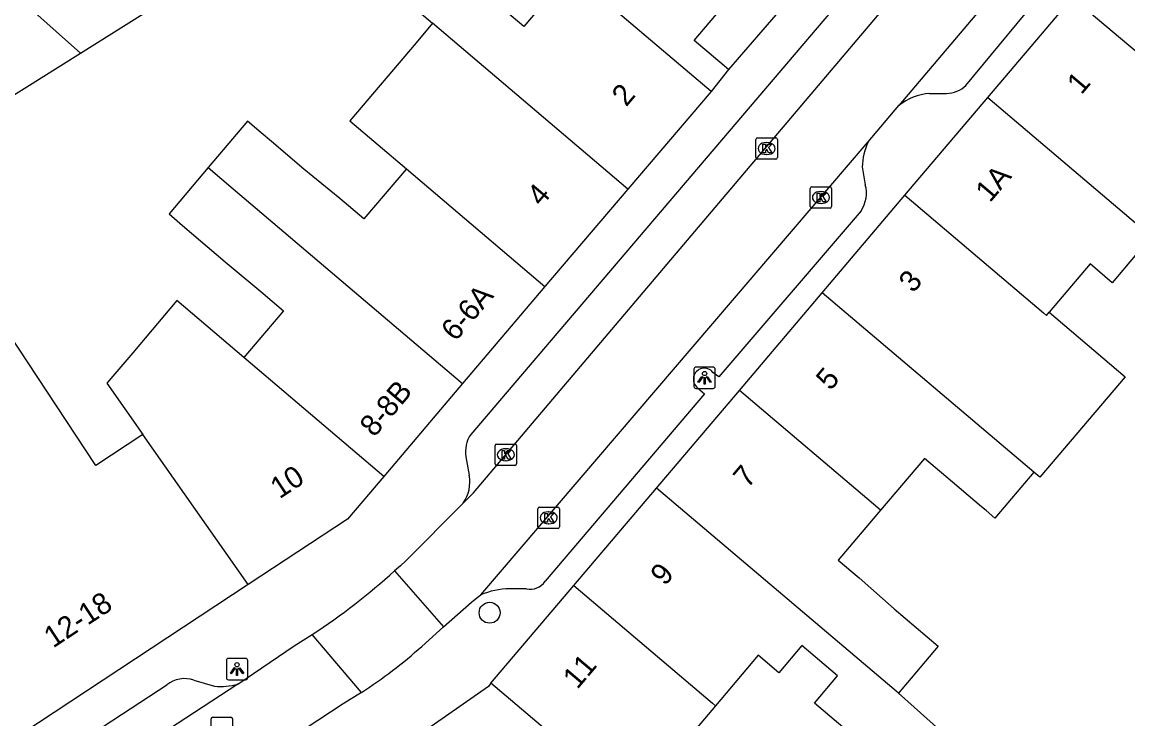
# Model space of a CAD drawing. Extents: x 161801 to 162379, y 382315 to 382832.
# Drawn here: x 162101.6 to 162153.3, y 382604.8 to 382637.3 of the extents above; entities that cross this region are included whole.
import ezdxf

# ---------------------------------------------------------------- set-up
doc = ezdxf.new("R2010")
doc.units = 0
for name, color, linetype in [('IMGEO_Boom', 7, 'Continuous'), ('IMGEO_Kolk', 7, 'Continuous'), ('IMGEO_Lichtpunt', 7, 'Continuous'), ('IMGEO_Pand', 7, 'Continuous'), ('IMGEO_Pand_nummerreeks', 7, 'Continuous'), ('IMGEO_Rijbaan_lokaal_open', 7, 'Continuous'), ('IMGEO_Rioolput', 7, 'Continuous'), ('IMGEO_Voetpad_open', 7, 'Continuous')]:
    doc.layers.add(name, color=color, linetype=linetype)

msp = doc.modelspace()

# ---------------------------------------------------------------- linework, layer by layer
at = {"layer": 'IMGEO_Boom'}
msp.add_circle((162123.501, 382609.719), 0.489, dxfattribs=at)
at = {"layer": 'IMGEO_Kolk'}
for p, q in [((162135.951, 382630.986), (162135.951, 382631.838)), ((162136.026, 382631.912), (162136.878, 382631.912)), ((162136.439, 382631.692), (162136.464, 382631.692)), ((162136.952, 382631.838), (162136.952, 382630.986)), ((162136.462, 382631.132), (162136.437, 382631.132)), ((162136.878, 382630.912), (162136.026, 382630.912)), ((162138.487, 382628.698), (162138.487, 382629.55)), ((162138.562, 382629.624), (162139.414, 382629.624)), ((162138.975, 382629.404), (162139, 382629.404)), ((162139.488, 382629.55), (162139.488, 382628.698)), ((162139.414, 382628.624), (162138.562, 382628.624)), ((162138.998, 382628.844), (162138.973, 382628.844)), ((162123.759, 382616.675), (162123.759, 382617.527)), ((162123.834, 382617.601), (162124.686, 382617.601)), ((162124.76, 382617.527), (162124.76, 382616.675)), ((162124.247, 382617.381), (162124.272, 382617.381)), ((162124.686, 382616.601), (162123.834, 382616.601)), ((162124.27, 382616.821), (162124.245, 382616.821)), ((162125.761, 382613.728), (162125.761, 382614.58)), ((162125.836, 382614.654), (162126.688, 382614.654)), ((162126.249, 382614.434), (162126.274, 382614.434)), ((162126.762, 382614.58), (162126.762, 382613.728)), ((162126.272, 382613.874), (162126.247, 382613.874)), ((162126.688, 382613.654), (162125.836, 382613.654))]:
    msp.add_line(p, q, dxfattribs=at)
for points in [[(162135.951, 382630.986), (162135.951, 382631.838)], [(162136.026, 382631.912), (162136.878, 382631.912)], [(162136.272, 382631.612), (162136.395, 382631.612), (162136.395, 382631.461), (162136.525, 382631.612), (162136.689, 382631.612), (162136.543, 382631.461), (162136.696, 382631.212), (162136.544, 382631.212), (162136.459, 382631.376), (162136.395, 382631.309), (162136.395, 382631.212), (162136.272, 382631.212), (162136.272, 382631.612)], [(162136.952, 382631.838), (162136.952, 382630.986)], [(162136.878, 382630.912), (162136.026, 382630.912)], [(162138.487, 382628.698), (162138.487, 382629.55)], [(162138.562, 382629.624), (162139.414, 382629.624)], [(162139.488, 382629.55), (162139.488, 382628.698)], [(162138.808, 382629.324), (162138.931, 382629.324), (162138.931, 382629.173), (162139.061, 382629.324), (162139.225, 382629.324), (162139.079, 382629.173), (162139.232, 382628.924), (162139.08, 382628.924), (162138.995, 382629.088), (162138.931, 382629.021), (162138.931, 382628.924), (162138.808, 382628.924), (162138.808, 382629.324)], [(162139.414, 382628.624), (162138.562, 382628.624)], [(162123.759, 382616.675), (162123.759, 382617.527)], [(162123.834, 382617.601), (162124.686, 382617.601)], [(162124.76, 382617.527), (162124.76, 382616.675)], [(162124.08, 382617.301), (162124.203, 382617.301), (162124.203, 382617.15), (162124.333, 382617.301), (162124.497, 382617.301), (162124.351, 382617.15), (162124.504, 382616.901), (162124.352, 382616.901), (162124.267, 382617.065), (162124.203, 382616.998), (162124.203, 382616.901), (162124.08, 382616.901), (162124.08, 382617.301)], [(162124.686, 382616.601), (162123.834, 382616.601)], [(162125.761, 382613.728), (162125.761, 382614.58)], [(162125.836, 382614.654), (162126.688, 382614.654)], [(162126.762, 382614.58), (162126.762, 382613.728)], [(162126.082, 382614.354), (162126.205, 382614.354), (162126.205, 382614.203), (162126.335, 382614.354), (162126.499, 382614.354), (162126.353, 382614.203), (162126.506, 382613.954), (162126.354, 382613.954), (162126.269, 382614.118), (162126.205, 382614.051), (162126.205, 382613.954), (162126.082, 382613.954), (162126.082, 382614.354)], [(162126.688, 382613.654), (162125.836, 382613.654)]]:
    msp.add_lwpolyline(points, dxfattribs=at)
for centre, start, end in [((162136.028, 382631.836), 91.552, 178.448), ((162136.028, 382631.836), 91.552, 178.448), ((162136.876, 382631.836), 1.552, 88.448), ((162136.876, 382631.836), 1.552, 88.448), ((162136.028, 382630.988), 181.552, 268.448), ((162136.028, 382630.988), 181.552, 268.448), ((162136.876, 382630.988), 271.552, 358.448), ((162136.876, 382630.988), 271.552, 358.448), ((162138.564, 382629.548), 91.552, 178.448), ((162138.564, 382629.548), 91.552, 178.448), ((162139.412, 382629.548), 1.552, 88.448), ((162139.412, 382629.548), 1.552, 88.448), ((162138.564, 382628.7), 181.552, 268.448), ((162138.564, 382628.7), 181.552, 268.448), ((162139.412, 382628.7), 271.552, 358.448), ((162139.412, 382628.7), 271.552, 358.448), ((162123.836, 382617.525), 91.552, 178.448), ((162123.836, 382617.525), 91.552, 178.448), ((162124.684, 382617.525), 1.552, 88.448), ((162124.684, 382617.525), 1.552, 88.448), ((162123.836, 382616.677), 181.552, 268.448), ((162123.836, 382616.677), 181.552, 268.448), ((162124.684, 382616.677), 271.552, 358.448), ((162124.684, 382616.677), 271.552, 358.448), ((162125.838, 382614.578), 91.552, 178.448), ((162125.838, 382614.578), 91.552, 178.448), ((162126.686, 382614.578), 1.552, 88.448), ((162126.686, 382614.578), 1.552, 88.448), ((162125.838, 382613.73), 181.552, 268.448), ((162125.838, 382613.73), 181.552, 268.448), ((162126.686, 382613.73), 271.552, 358.448), ((162126.686, 382613.73), 271.552, 358.448)]:
    msp.add_arc(centre, 0.0765, start, end, dxfattribs=at)
for centre, major_axis, ratio, start_param, end_param in [((162136.438, 382631.412), (-0.387, 0.002), 0.722429, 4.712389, 7.853982), ((162136.463, 382631.412), (-0.39, 0.002), 0.717154, 1.570796, 4.712389), ((162138.974, 382629.124), (-0.387, 0.002), 0.722429, 4.712389, 7.853982), ((162138.999, 382629.124), (-0.39, 0.002), 0.717154, 1.570796, 4.712389), ((162124.246, 382617.101), (-0.387, 0.002), 0.722429, 4.712389, 7.853982), ((162124.271, 382617.101), (-0.39, 0.002), 0.717154, 1.570796, 4.712389), ((162126.248, 382614.154), (-0.387, 0.002), 0.722429, 4.712389, 7.853982), ((162126.273, 382614.154), (-0.39, 0.002), 0.717154, 1.570796, 4.712389)]:
    msp.add_ellipse(centre, major_axis=major_axis, ratio=ratio, start_param=start_param, end_param=end_param, dxfattribs=at)
at = {"layer": 'IMGEO_Lichtpunt'}
for p, q in [((162133.048, 382621.1), (162133.048, 382620.293)), ((162133.048, 382621.1), (162133.048, 382620.293)), ((162133.95, 382621.195), (162133.142, 382621.195)), ((162133.95, 382621.195), (162133.142, 382621.195)), ((162134.044, 382620.293), (162134.044, 382621.1)), ((162134.044, 382620.293), (162134.044, 382621.1)), ((162133.142, 382620.199), (162133.95, 382620.199)), ((162133.142, 382620.199), (162133.95, 382620.199)), ((162111.194, 382607.489), (162111.194, 382606.682)), ((162111.194, 382607.489), (162111.194, 382606.682)), ((162112.096, 382607.584), (162111.288, 382607.584)), ((162112.096, 382607.584), (162111.288, 382607.584)), ((162112.19, 382606.682), (162112.19, 382607.489)), ((162112.19, 382606.682), (162112.19, 382607.489)), ((162111.288, 382606.588), (162112.096, 382606.588)), ((162111.288, 382606.588), (162112.096, 382606.588))]:
    msp.add_line(p, q, dxfattribs=at)
for points in [[(162133.422, 382620.764), (162133.461, 382620.736), (162133.273, 382620.474), (162133.235, 382620.501), (162133.422, 382620.764)], [(162133.524, 382620.716), (162133.571, 382620.716), (162133.571, 382620.394), (162133.524, 382620.394), (162133.524, 382620.716)], [(162133.634, 382620.736), (162133.672, 382620.763), (162133.859, 382620.501), (162133.82, 382620.473), (162133.634, 382620.736)], [(162111.568, 382607.153), (162111.607, 382607.125), (162111.419, 382606.863), (162111.381, 382606.89), (162111.568, 382607.153)], [(162111.78, 382607.125), (162111.818, 382607.152), (162112.005, 382606.89), (162111.966, 382606.862), (162111.78, 382607.125)], [(162111.67, 382607.105), (162111.717, 382607.105), (162111.717, 382606.783), (162111.67, 382606.783), (162111.67, 382607.105)]]:
    msp.add_lwpolyline(points, dxfattribs=at)
for centre in [(162133.547, 382620.898), (162111.693, 382607.287)]:
    msp.add_circle(centre, 0.0994, dxfattribs=at)
for centre, start, end in [((162133.142, 382621.1), 90, 180), ((162133.142, 382621.1), 90, 180), ((162133.95, 382621.1), 0, 90), ((162133.95, 382621.1), 0, 90), ((162133.142, 382620.293), 180, 270), ((162133.142, 382620.293), 180, 270), ((162133.95, 382620.293), 270, 0), ((162133.95, 382620.293), 270, 360), ((162111.288, 382607.489), 90, 180), ((162111.288, 382607.489), 90, 180), ((162112.096, 382607.489), 0, 90), ((162112.096, 382607.489), 0, 90), ((162111.288, 382606.682), 180, 270), ((162111.288, 382606.682), 180, 270), ((162112.096, 382606.682), 270, 0), ((162112.096, 382606.682), 270, 360)]:
    msp.add_arc(centre, 0.0946, start, end, dxfattribs=at)
at = {"layer": 'IMGEO_Pand'}
for points in [[(162147.319, 382649.725), (162134.661, 382635.1)], [(162134.661, 382635.1), (162133.06, 382636.459), (162135.001, 382638.746), (162133.762, 382639.798), (162138.222, 382645.133), (162136.061, 382646.496)], [(162133.856, 382634.079), (162127.271, 382639.672), (162125.102, 382637.119), (162123.327, 382638.627), (162123.644, 382639.001), (162120.214, 382641.914), (162118.181, 382639.521), (162120.834, 382637.267)], [(162104.377, 382635.872), (162107.299, 382637.712), (162105.117, 382641.18)], [(162104.377, 382635.872), (162102.104, 382637.898), (162101.503, 382638.903)], [(162146.784, 382633.798), (162150.752, 382638.476)], [(162150.752, 382638.476), (162154.546, 382635.258), (162157.427, 382632.815), (162155.342, 382630.356), (162156.314, 382629.532), (162155.23, 382628.253), (162156.914, 382626.824), (162157.985, 382628.086), (162160.094, 382626.297), (162158.226, 382624.094)], [(162120.834, 382637.267), (162120.061, 382636.357), (162116.961, 382632.708), (162119.612, 382630.456)], [(162129.957, 382629.519), (162120.834, 382637.267)], [(162098.642, 382637.101), (162100.825, 382633.634), (162104.377, 382635.872)], [(162133.856, 382634.079), (162129.957, 382629.519)], [(162142.914, 382629.235), (162146.784, 382633.798)], [(162146.784, 382633.798), (162158.226, 382624.094)], [(162119.612, 382630.456), (162117.627, 382628.119), (162116.502, 382629.075), (162114.819, 382630.45), (162113.31, 382631.732), (162112.822, 382632.146), (162112.187, 382632.685), (162110.35, 382630.522)], [(162110.35, 382630.522), (162108.513, 382628.359), (162109.148, 382627.819), (162111.143, 382626.124), (162112.801, 382624.729), (162113.868, 382623.823), (162112.014, 382621.641)], [(162110.35, 382630.522), (162110.985, 382629.982), (162111.512, 382629.534), (162122.235, 382620.427)], [(162119.612, 382630.456), (162126.084, 382624.959)], [(162129.957, 382629.519), (162126.084, 382624.959)], [(162139.044, 382624.672), (162142.914, 382629.235)], [(162142.914, 382629.235), (162149.395, 382623.739), (162149.537, 382623.616), (162149.656, 382623.757)], [(162158.226, 382624.094), (162156.409, 382621.952), (162154.269, 382623.768), (162155.33, 382625.019), (162153.684, 382626.414), (162152.605, 382625.142), (162151.574, 382626.017), (162149.656, 382623.757)], [(162126.084, 382624.959), (162122.235, 382620.427)], [(162107.295, 382618.041), (162105.098, 382616.595), (162100.999, 382622.82), (162100.9, 382622.755), (162099.695, 382624.586), (162096.703, 382622.616), (162096.461, 382622.456), (162093.624, 382620.587), (162098.869, 382612.622), (162096.136, 382610.823)], [(162112.014, 382621.641), (162108.881, 382624.302), (162106.815, 382621.87), (162105.604, 382620.445), (162107.295, 382618.041)], [(162135.174, 382620.109), (162139.044, 382624.672)], [(162148.933, 382616.285), (162139.044, 382624.672)], [(162149.656, 382623.757), (162153.203, 382620.746), (162149.214, 382616.047), (162148.933, 382616.285)], [(162118.549, 382616.087), (162112.014, 382621.641)], [(162122.235, 382620.427), (162118.549, 382616.087)], [(162131.303, 382615.547), (162135.174, 382620.109)], [(162141.779, 382614.505), (162141.651, 382614.616), (162135.174, 382620.109)], [(162112.221, 382611.038), (162107.295, 382618.041)], [(162148.933, 382616.285), (162147.117, 382614.144), (162146.705, 382614.493), (162146.495, 382614.671), (162144.829, 382616.078), (162143.831, 382616.924), (162141.779, 382614.505)], [(162118.549, 382616.087), (162116.85, 382614.086), (162112.221, 382611.038)], [(162127.433, 382610.984), (162131.303, 382615.547)], [(162142.607, 382605.955), (162142.503, 382606.048), (162131.303, 382615.547)], [(162141.779, 382614.505), (162139.801, 382612.174), (162140.773, 382611.35), (162142.417, 382609.898), (162144.473, 382608.155), (162143.028, 382606.452), (162142.773, 382606.151), (162142.607, 382605.955)], [(162112.221, 382611.038), (162100.902, 382603.585)], [(162123.564, 382606.422), (162127.433, 382610.984)], [(162127.433, 382610.984), (162133.915, 382605.487), (162134.054, 382605.366)], [(162142.607, 382605.955), (162144.965, 382603.857), (162143.567, 382602.209), (162141.15, 382604.258), (162140.73, 382603.763), (162138.684, 382605.498), (162139.761, 382606.768), (162138.09, 382608.185), (162137.016, 382606.918), (162136.059, 382607.73), (162134.054, 382605.366)], [(162123.564, 382606.422), (162123.441, 382606.277), (162119.59, 382603.578)], [(162134.825, 382596.872), (162123.564, 382606.422)], [(162134.054, 382605.366), (162132.076, 382603.035), (162133.05, 382602.209), (162131.977, 382600.944), (162133.592, 382599.574), (162134.647, 382600.817), (162136.697, 382599.078), (162134.825, 382596.872)]]:
    msp.add_lwpolyline(points, dxfattribs=at)
at = {"layer": 'IMGEO_Rijbaan_lokaal_open'}
for points in [[(162122.269, 382614.843), (162122.753, 382615.329), (162149.054, 382646.389), (162149.787, 382647.279)], [(162152.692, 382645.309), (162142.626, 382633.419)], [(162141.201, 382631.731), (162142.626, 382633.419)], [(162123.083, 382610.549), (162141.201, 382631.731)], [(162122.269, 382614.843), (162119.59, 382612.152), (162119.338, 382611.918), (162119.058, 382611.678)], [(162119.058, 382611.678), (162121.344, 382609.054)], [(162121.344, 382609.054), (162122.651, 382610.22), (162122.988, 382610.477), (162123.083, 382610.549)], [(162111.73, 382606.38), (162114.363, 382608.167), (162115.212, 382608.704)], [(162117.507, 382605.989), (162115.212, 382608.704)], [(162121.344, 382609.054), (162120.329, 382608.149)], [(162111.73, 382606.38), (162087.354, 382590.455)], [(162117.507, 382605.989), (162116.651, 382605.458), (162114.877, 382604.291), (162110.359, 382601.34)]]:
    msp.add_lwpolyline(points, dxfattribs=at)
for centre, radius, start, end in [((162098.38, 382634.446), 30.756, 303.1806, 312.2469), ((162104.787, 382625.531), 23.318, 303.0606, 311.8013)]:
    msp.add_arc(centre, radius, start, end, dxfattribs=at)
at = {"layer": 'IMGEO_Rioolput'}
for p, q in [((162110.481, 382603.907), (162110.481, 382604.759)), ((162110.556, 382604.833), (162111.408, 382604.833)), ((162111.482, 382604.759), (162111.482, 382603.907))]:
    msp.add_line(p, q, dxfattribs=at)
for points in [[(162110.481, 382603.907), (162110.481, 382604.759)], [(162110.556, 382604.833), (162111.408, 382604.833)], [(162111.482, 382604.759), (162111.482, 382603.907)]]:
    msp.add_lwpolyline(points, dxfattribs=at)
for centre, start, end in [((162110.558, 382604.757), 91.552, 178.448), ((162110.558, 382604.757), 91.552, 178.448), ((162111.406, 382604.757), 1.552, 88.448), ((162111.406, 382604.757), 1.552, 88.448)]:
    msp.add_arc(centre, 0.0765, start, end, dxfattribs=at)
at = {"layer": 'IMGEO_Voetpad_open'}
for points in [[(162146.559, 382646.195), (162144.095, 382643.304), (162140.871, 382639.485), (162122.616, 382618.055)], [(162145.768, 382634.361), (162149.742, 382639.173), (162152.277, 382642.167)], [(162134.661, 382635.1), (162133.856, 382634.079)], [(162144.068, 382633.987), (162144.855, 382633.989)], [(162140.918, 382630.548), (162141.061, 382629.711)], [(162140.862, 382628.504), (162134.222, 382620.75), (162133.942, 382620.952)], [(162133.221, 382620.226), (162133.552, 382619.948), (162126.091, 382611.188)], [(162122.391, 382617), (162122.546, 382616.151)], [(162125.228, 382610.829), (162124.429, 382610.839)], [(162088.725, 382593.485), (162108.41, 382606.351)], [(162109.679, 382606.571), (162110.645, 382606.283)]]:
    msp.add_lwpolyline(points, dxfattribs=at)
for centre, radius, start, end in [((162144.853, 382635.3), 1.311, 270.0841, 314.2526), ((162144.283, 382631.326), 2.67, 94.6244, 128.3743), ((162143.739, 382630.499), 2.821, 154.0969, 178.9959), ((162139.653, 382629.323), 1.461, 325.8819, 15.3937), ((162133.538, 382620.632), 0.515, 38.4258, 231.9701), ((162123.883, 382617.233), 1.51, 147.0294, 188.8924), ((162120.847, 382615.827), 1.729, 325.3, 10.7859), ((162124.465, 382607.401), 3.438, 90.6074, 113.71), ((162125.385, 382611.669), 0.854, 259.4161, 325.7577), ((162109.25, 382605.274), 1.366, 71.701, 127.9697), ((162110.934, 382609.164), 2.895, 264.2649, 285.9526)]:
    msp.add_arc(centre, radius, start, end, dxfattribs=at)

# ---------------------------------------------------------------- texts
at = {"layer": 'IMGEO_Pand_nummerreeks'}
for s, rotation, p in [('1', 49.6956, (162151.165, 382633.892)), ('2', 49.6583, (162129.886, 382633.328)), ('1A', 49.6984, (162146.889, 382628.851)), ('4', 49.6583, (162125.921, 382628.66)), ('3', 49.6984, (162143.303, 382624.622)), ('6-6A', 49.6583, (162121.908, 382622.36)), ('5', 49.6984, (162139.433, 382620.059)), ('8-8B', 49.6583, (162118.107, 382617.884)), ('10', 33.3633, (162113.679, 382615.015)), ('7', 49.6984, (162135.563, 382615.496)), ('9', 49.6984, (162131.693, 382610.933)), ('12-18', 33.3633, (162103.094, 382608.045)), ('11', 49.6981, (162127.6, 382606.107))]:
    msp.add_text(s, height=1, rotation=rotation, dxfattribs=at).set_placement(p)

doc.saveas('drawing.dxf')
